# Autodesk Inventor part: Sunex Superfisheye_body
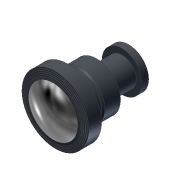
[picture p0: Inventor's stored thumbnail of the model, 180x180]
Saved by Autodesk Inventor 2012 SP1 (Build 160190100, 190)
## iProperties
Created: 2012-03
Part Number: Sunex Superfisheye_body
Material: Aluminum-6061
Document SubType Name: Modeling
Designer: jdh
Density: 2.71 g/cm^3
Mass: 422.615 g
Surface Area: 203.493 cm^2
Volume: 155.947 cm^3
Author: jdh
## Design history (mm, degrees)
sketch "Sketch1"
  geometry: L1 (0, 0)-(0, 94.539); L2 (0, 0)-(24.902, 0); L3 (0, 94.539)-(24.902, 94.539); L4 (0, 3.886)-(8.471, 3.886); L5 (9.036, 10.82)-(20.936, 10.82); L6 (-1.25, 37.313)-(24.892, 37.313); L7 (0, 61.392)-(24.892, 61.392); L8 (8.471, 3.886)-(8.471, 0); L9 (8.471, 3.886)-(20.936, 3.886); L10 (20.936, 3.886)-(20.936, 10.82); L11 (20.936, 10.82)-(14.986, 10.82); L12 (14.986, 37.313)-(14.986, 10.82); L13 (14.986, 37.313)-(24.892, 37.313); L14 (24.892, 53.569)-(24.892, 37.313); L15 (24.892, 57.074)-(24.892, 61.392); L16 (24.892, 57.074)-(23.139, 55.321); L17 (24.892, 53.569)-(23.139, 55.321); L18 (0, 67.107)-(34.963, 67.107); L19 (34.963, 67.107)-(34.963, 80.315); L20 (34.963, 67.107)-(24.892, 61.392); L21 (34.963, 80.315)-(33.566, 80.315); L22 (33.566, 80.315)-(33.566, 80.823); L23 (33.566, 80.823)-(32.245, 80.823); L24 (32.245, 80.823)-(32.245, 81.331); L25 (32.245, 81.331)-(30.848, 81.331); L26 (30.848, 81.331)-(30.848, 81.839); L27 (30.848, 81.839)-(29.451, 81.839); L28 (29.451, 81.839)-(29.451, 82.347); L29 (29.451, 82.347)-(28.092, 82.347); L30 (28.092, 82.347)-(25.717, 82.702); L31 (24.902, 94.539)-(24.902, 73.05); L32 (24.902, 73.05)-(0, 73.05); L33 (0, 88.697)-(-18.083, 88.697); L34 (8.471, 0)-(5.677, 0); L35 (5.677, 0)-(5.677, 1.016); L36 (0, -0.254)-(-3.429, -0.254); L37 (0, -0.254)-(0, 88.697); A1 r 58.165 centre (0, 30.532) between (25.717, 82.702) and (0, 88.697); A2 r 13.323 centre (0, 13.069) between (0, -0.254) and (5.677, 1.016)
  constraints: 74 end point, 18 perpendicular, 9 parallel, 6 point on line, 4 collinear, 4 equal length, 4 point on circle, 2 centre point, 2 tangent, 1 midpoint, 1 vertical
  dimensions: "d1" = 94.5388 distance between parallel lines of L2 L3; "d2" = 3.8862 distance between parallel lines of L4 L2; "d3" = 6.9342 distance between parallel lines of L4 L5; "d4" = 26.4922 distance between parallel lines of L5 L6; "d5" = 24.0792 distance between parallel lines of L6 L7; "d6" = 16.9418 diameter of L8 L1; "d7" = 41.8719 diameter of L10 L1; "d8" = 29.972 diameter of L12 L1; "d9" = 49.784 diameter of L14 L1; "d10" = 16.256 distance of L14.start L6.end; "d11" = 4.318 distance of L15.start L7.end; "d12" = 90 deg angle of L17 L16; "d13" = 27.432 distance between parallel lines of L18 L3; "d14" = 69.9262 diameter of L19 L1; "d15" = 13.208 distance of L18.end L19.end; "d16" = 67.1322 diameter of L22 L1; "d17" = 64.4906 diameter of L24 L1; "d18" = 61.6966 diameter of L26 L1; "d19" = 58.9026 diameter of L28 L1; "d20" = 0.508 distance of L21.end L22.end; "d21" = 21.4884 distance of L3.end L31.end; "d22" = 6.35 distance between parallel lines of L33 L29; "d23" = 56.1848 diameter of L29.end L1; "d24" = 51.435 diameter of L30.end L1; "d25" = 0.8636 distance from line of L30.end L27; "d26" = 2.794 distance from line of L35.end L8; "d27" = 0.254 distance between parallel lines of L36 L34; "d28" = 1.016 distance of L34.end L35.end
revolve "Revolution1" sketch "Sketch1" stored, may be unused: angle "d29" = 90 deg
body "Solid1"
